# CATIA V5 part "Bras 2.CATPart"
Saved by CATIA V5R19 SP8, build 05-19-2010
Part number: Bras 2
Bounding box of the stored display mesh (mm): x -560 to -516, y -30 to 115.652, z -30 to 335.41
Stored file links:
  G:\EU_thinkMotion\CFAO_2010\MMS_groupe1\MMS_groupe1\OK\rragonneau\rragonneau\Bras 2.CATPart
  D:\Documents\Scolaire\MM2\CFAO\Brevet\MODELE CATIA\Squelette\Deambulateur.CATProduct
  G:\EU_thinkMotion\CFAO_2010\MMS_groupe1\MMS_groupe1\OK\rragonneau\rragonneau\squelette bras 2.CATPart
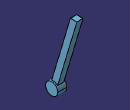
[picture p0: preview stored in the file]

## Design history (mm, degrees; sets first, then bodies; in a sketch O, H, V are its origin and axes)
External parameters (linked from other documents)
  `External.diam_moyeu_ext / epaisseur_bras&montant` = 60 mm
Set1
  Sketch1 on Plane1, origin (-538, 0, 0), H (0, 1, 0), V (0, 0, 1)
    circle A1 centre (0, 0) radius 30
    radius A1 = 30 {= `External.diam_moyeu_ext / epaisseur_bras&montant` /2}
  Sketch2 on Plane1, origin (-538, 0, 0), H (0, 1, 0), V (0, 0, 1)
    line L1 (84.3475, 335.4102) -> (115.6525, 335.4102)
    line L2 (115.6525, 335.4102) -> (17.8885, 7.5)
    line L3 (17.8885, 7.5) -> (-13.4164, 7.5)
    line L4 (-13.4164, 7.5) -> (84.3475, 335.4102)
    reference intersected line E1 through (0, 335.4102) direction (-1, 0) from Plane2
    reference projected line E2 (171.4286, 574.9889) -> (0, 0) from Line1
    reference projected line E3 (171.4286, 574.9889) -> (0, 0) from Line1
    reference projected line E4 (171.4286, 574.9889) -> (0, 0) from Line1
    reference projected line E5 (171.4286, 574.9889) -> (0, 0) from Line1
    distance L2 E4 = 15 {= `External.diam_moyeu_ext / epaisseur_bras&montant` /4}
    distance L4 E5 = 15 {= `External.diam_moyeu_ext / epaisseur_bras&montant` /4}
    distance L3 H = 7.5 {= `External.diam_moyeu_ext / epaisseur_bras&montant` /8}
    horizontal: L3 H, L1 H
    coincidence: L1 E1
    parallelism: E2 L2, L4 E3
Set2
  Plane1: linked copy from another document
  Plane2: linked copy from another document
  Line1: linked copy from another document
Body1 (main body)
  Pad1: profile Sketch1, direction (1, 0, 0), length 22 {= `External.diam_moyeu_ext / epaisseur_bras&montant` /4+7mm}, opposite side length 22 {= `External.diam_moyeu_ext / epaisseur_bras&montant` /4+7mm}
  Pad2: profile Sketch2, direction (1, 0, 0), length 15 {= `External.diam_moyeu_ext / epaisseur_bras&montant` /4}, opposite side length 15 {= `External.diam_moyeu_ext / epaisseur_bras&montant` /4}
